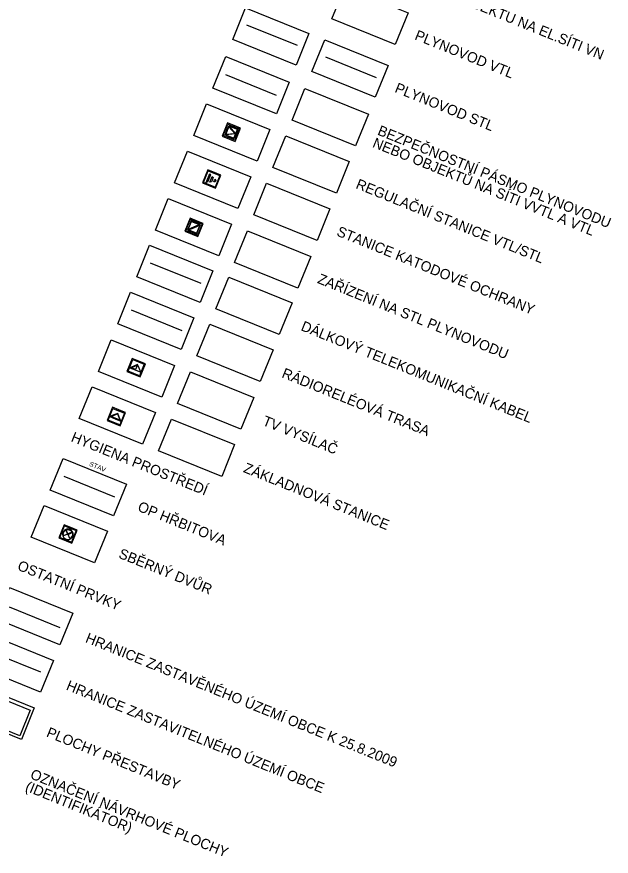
# Model space of a CAD drawing. Extents: x -522754 to -518969, y -1191121 to -1188171.
# Drawn here: x -520123 to -519254, y -1191121 to -1189893 of the extents above; entities that cross this region are included whole.
import ezdxf

# ---------------------------------------------------------------- set-up
doc = ezdxf.new("R2010")
doc.units = 0
for name, color, linetype in [('hr_zast_uz_P_n', 7, 'Continuous'), ('HZU_P_s', 7, 'Continuous'), ('Implicitní', 7, 'Continuous'), ('kabel_dal_s', 7, 'Continuous'), ('ložisk_nerost', 7, 'Continuous'), ('plyn_STL_n', 7, 'Continuous'), ('plyn_STL_s', 7, 'Continuous'), ('plyn_zar_STL_s', 7, 'Continuous'), ('RR_trasa_s', 7, 'Continuous'), ('sberny_dvur_s', 7, 'Continuous'), ('stan_KO_s', 7, 'Continuous'), ('TV_vysilac_s', 7, 'Continuous'), ('zakl_stan_s', 7, 'Continuous')]:
    doc.layers.add(name, color=color, linetype=linetype)

msp = doc.modelspace()

# ---------------------------------------------------------------- linework, layer by layer
at = {"layer": 'hr_zast_uz_P_n'}
msp.add_line((-520162.9, -1190821.2), (-520088.7, -1190851.2), dxfattribs=at)
at = {"layer": 'HZU_P_s'}
msp.add_line((-520134.5, -1190756.1), (-520060.4, -1190786.2), dxfattribs=at)
at = {"layer": 'Implicitní'}
for p, q in [((-519818.1, -1189977.4), (-519744, -1190007.5)), ((-520054.8, -1190564.9), (-519980.6, -1190594.9))]:
    msp.add_line(p, q, dxfattribs=at)
for points in [[(-519643.7, -1189849.5), (-519551, -1189887.1), (-519569.8, -1189933.4), (-519662.5, -1189895.8)], [(-519788.7, -1189879.6), (-519696, -1189917.2), (-519714.8, -1189963.5), (-519807.5, -1189925.9)], [(-519672.9, -1189926.6), (-519580.2, -1189964.1), (-519599, -1190010.5), (-519691.7, -1189972.9)], [(-519817.6, -1189950.9), (-519724.9, -1189988.4), (-519743.7, -1190034.8), (-519836.4, -1189997.2)], [(-519701.8, -1189997.8), (-519609.1, -1190035.4), (-519627.9, -1190081.7), (-519720.5, -1190044.2)], [(-519845.7, -1190020.2), (-519753, -1190057.8), (-519771.8, -1190104.1), (-519864.5, -1190066.5)], [(-519729.8, -1190067.1), (-519637.2, -1190104.7), (-519655.9, -1190151), (-519748.6, -1190113.5)], [(-519873.8, -1190089.5), (-519781.1, -1190127.1), (-519799.9, -1190173.4), (-519892.6, -1190135.8)], [(-519757.9, -1190136.4), (-519665.3, -1190174), (-519684, -1190220.3), (-519776.7, -1190182.8)], [(-519901.9, -1190158.8), (-519809.2, -1190196.4), (-519828, -1190242.7), (-519920.7, -1190205.1)], [(-519786, -1190205.8), (-519693.3, -1190243.3), (-519712.1, -1190289.7), (-519804.8, -1190252.1)], [(-519929.1, -1190226.8), (-519836.4, -1190264.3), (-519855.2, -1190310.7), (-519947.9, -1190273.1)], [(-519813.3, -1190273.7), (-519720.6, -1190311.3), (-519739.4, -1190357.6), (-519832, -1190320.1)], [(-519957, -1190295.6), (-519864.3, -1190333.2), (-519883.1, -1190379.5), (-519975.8, -1190342)], [(-519957, -1190295.6), (-519864.3, -1190333.2), (-519883.1, -1190379.5), (-519975.8, -1190342)], [(-519841.2, -1190342.6), (-519748.5, -1190380.1), (-519767.3, -1190426.5), (-519859.9, -1190388.9)], [(-519985.3, -1190365.4), (-519892.6, -1190402.9), (-519911.4, -1190449.3), (-520004.1, -1190411.7)], [(-519869.4, -1190412.3), (-519776.8, -1190449.9), (-519795.5, -1190496.2), (-519888.2, -1190458.7)], [(-520013.2, -1190434.2), (-519920.5, -1190471.8), (-519939.3, -1190518.1), (-520032, -1190480.6)], [(-520013.2, -1190434.2), (-519920.5, -1190471.8), (-519939.3, -1190518.1), (-520032, -1190480.6)], [(-519897.3, -1190481.2), (-519804.7, -1190518.7), (-519823.4, -1190565.1), (-519916.1, -1190527.5)], [(-520055.6, -1190539), (-519962.9, -1190576.5), (-519981.7, -1190622.9), (-520074.4, -1190585.3)], [(-520083.5, -1190607.8), (-519990.8, -1190645.4), (-520009.6, -1190691.7), (-520102.3, -1190654.2)], [(-520134.3, -1190727.5), (-520041.6, -1190765), (-520060.4, -1190811.4), (-520153, -1190773.8)], [(-520162.4, -1190797), (-520069.7, -1190834.5), (-520088.5, -1190880.9), (-520181.2, -1190843.3)], [(-520190.5, -1190866.2), (-520097.8, -1190903.8), (-520116.6, -1190950.1), (-520209.3, -1190912.6)], [(-520187.6, -1190872.9), (-520103.8, -1190907), (-520119.1, -1190944.5), (-520202.9, -1190910.4)]]:
    msp.add_lwpolyline(points, close=True, dxfattribs=at)
at = {"layer": 'kabel_dal_s'}
msp.add_line((-519928.3, -1190252.7), (-519854.1, -1190282.7), dxfattribs=at)
at = {"layer": 'ložisk_nerost'}
for points in [[(-519805.6, -1190052), (-519815.3, -1190048.1), (-519823, -1190067.4), (-519803.7, -1190075.2), (-519796, -1190055.9), (-519805.6, -1190052)], [(-519814.5, -1190049.8), (-519797.6, -1190056.6), (-519804.4, -1190073.5), (-519821.4, -1190066.7), (-519814.5, -1190049.8)], [(-519806.1, -1190053.2), (-519797.6, -1190056.6), (-519804.4, -1190073.5), (-519821.4, -1190066.7), (-519814.5, -1190049.8), (-519806.1, -1190053.2)], [(-519812, -1190068.4), (-519818.8, -1190065.7), (-519816.1, -1190059)], [(-519815.5, -1190059.2), (-519817.7, -1190064.6)], [(-519816.1, -1190058.9), (-519813.4, -1190052.2), (-519806.6, -1190054.9)], [(-519815.5, -1190059.2), (-519816.1, -1190058.9)], [(-519816.1, -1190059), (-519815.5, -1190059.2)], [(-519813.3, -1190053.7), (-519815.5, -1190059.2)], [(-519804.6, -1190063.6), (-519813.3, -1190053.7)], [(-519806.9, -1190055.5), (-519813, -1190053)], [(-519813, -1190053), (-519803.2, -1190064.1)], [(-519806.6, -1190054.9), (-519806.9, -1190055.5)], [(-519806.8, -1190055.5), (-519806.6, -1190054.9)], [(-519800.7, -1190058), (-519806.8, -1190055.5)], [(-519806.6, -1190054.9), (-519799.9, -1190057.6), (-519802.6, -1190064.4)], [(-519805.6, -1190052), (-519806.1, -1190053.2)], [(-519806.1, -1190053.2), (-519805.6, -1190052)], [(-519805.7, -1190070.3), (-519800.7, -1190058)], [(-519803.2, -1190064.1), (-519818, -1190065.4)], [(-519818, -1190065.4), (-519811.8, -1190067.9)], [(-519817.7, -1190064.6), (-519804.6, -1190063.6)], [(-519802.6, -1190064.4), (-519805.3, -1190071.2), (-519812, -1190068.4)], [(-519811.8, -1190067.9), (-519805.7, -1190070.3)]]:
    msp.add_lwpolyline(points, dxfattribs=at)
at = {"layer": 'plyn_STL_n'}
msp.add_line((-519671.7, -1189951.5), (-519597.5, -1189981.5), dxfattribs=at)
at = {"layer": 'plyn_STL_s'}
msp.add_line((-519787.5, -1189904.5), (-519713.4, -1189934.6), dxfattribs=at)
at = {"layer": 'plyn_zar_STL_s'}
for p, q in [((-519856.1, -1190196.9), (-519864.8, -1190200.6)), ((-519861.7, -1190194.7), (-519861.4, -1190194.1)), ((-519861.4, -1190194.1), (-519861.6, -1190194.7)), ((-519864.8, -1190200.6), (-519872.6, -1190203.9)), ((-519872.2, -1190204.7), (-519864.4, -1190201.4)), ((-519866.9, -1190207.6), (-519866.7, -1190207)), ((-519866.6, -1190207), (-519866.9, -1190207.6)), ((-519864.4, -1190201.4), (-519855.7, -1190197.8))]:
    msp.add_line(p, q, dxfattribs=at)
for points in [[(-519860.3, -1190191.2), (-519869.9, -1190187.3), (-519877.7, -1190206.6), (-519858.4, -1190214.4), (-519850.6, -1190195.1), (-519860.3, -1190191.2)], [(-519869.2, -1190189), (-519852.3, -1190195.8), (-519859.1, -1190212.7), (-519876, -1190205.9), (-519869.2, -1190189)], [(-519860.7, -1190192.4), (-519852.3, -1190195.8), (-519859.1, -1190212.7), (-519876, -1190205.9), (-519869.2, -1190189), (-519860.8, -1190192.4)], [(-519861.4, -1190194.1), (-519868.2, -1190191.3), (-519870.9, -1190198.1)], [(-519870.3, -1190198.3), (-519867.8, -1190192.2)], [(-519867.8, -1190192.2), (-519861.7, -1190194.7)], [(-519861.6, -1190194.7), (-519856.1, -1190196.9)], [(-519857.4, -1190203.6), (-519854.7, -1190196.8), (-519861.4, -1190194.1)], [(-519860.8, -1190192.4), (-519860.3, -1190191.2)], [(-519860.3, -1190191.2), (-519860.7, -1190192.4)], [(-519870.9, -1190198.1), (-519873.7, -1190204.9), (-519866.9, -1190207.6)], [(-519872.6, -1190203.9), (-519870.3, -1190198.3)], [(-519866.7, -1190207), (-519872.2, -1190204.7)], [(-519866.9, -1190207.6), (-519860.1, -1190210.3), (-519857.4, -1190203.6)], [(-519860.5, -1190209.5), (-519866.6, -1190207)], [(-519858, -1190203.3), (-519860.5, -1190209.5)], [(-519855.7, -1190197.8), (-519858, -1190203.3)]]:
    msp.add_lwpolyline(points, dxfattribs=at)
at = {"layer": 'RR_trasa_s'}
msp.add_line((-519956.2, -1190321.5), (-519882, -1190351.6), dxfattribs=at)
at = {"layer": 'sberny_dvur_s'}
for points in [[(-520044.5, -1190639.8), (-520054.1, -1190635.9), (-520062, -1190655.2), (-520042.7, -1190663), (-520034.9, -1190643.8), (-520044.5, -1190639.9)], [(-520053.4, -1190637.6), (-520036.5, -1190644.5), (-520043.4, -1190661.4), (-520060.3, -1190654.5), (-520053.4, -1190637.6)], [(-520045, -1190641), (-520036.5, -1190644.5), (-520043.4, -1190661.4), (-520060.3, -1190654.5), (-520053.4, -1190637.6), (-520045, -1190641)], [(-520056, -1190647.5), (-520056.2, -1190648.4), (-520056.3, -1190649.4), (-520056.3, -1190650.3), (-520056.2, -1190651.3), (-520055.9, -1190652.2), (-520055.5, -1190653.1), (-520055.1, -1190654), (-520054.5, -1190654.8), (-520053.8, -1190655.4), (-520053, -1190656), (-520052.2, -1190656.5), (-520051.6, -1190656.8)], [(-520055.8, -1190646.8), (-520056, -1190647.4), (-520056, -1190647.5)], [(-520054.9, -1190647.1), (-520055.8, -1190646.8)], [(-520045.8, -1190642.6), (-520046, -1190642.5), (-520046.9, -1190642.2), (-520047.9, -1190642.1), (-520048.9, -1190642), (-520049.8, -1190642.1), (-520050.8, -1190642.3), (-520051.7, -1190642.7), (-520052.6, -1190643.1), (-520053.4, -1190643.7), (-520054.1, -1190644.3), (-520054.7, -1190645), (-520055.3, -1190645.8), (-520055.7, -1190646.7), (-520055.7, -1190646.7)], [(-520055.7, -1190646.7), (-520054.9, -1190647.1)], [(-520055, -1190652.1), (-520055.2, -1190651.4), (-520055.3, -1190650.6), (-520055.4, -1190649.7), (-520055.4, -1190648.9), (-520055.2, -1190648.1), (-520055.1, -1190647.8)], [(-520055.1, -1190647.8), (-520054.9, -1190647.1)], [(-520049.1, -1190649.6), (-520055, -1190652.1)], [(-520054.9, -1190647.1), (-520054.6, -1190646.6)], [(-520054.6, -1190646.6), (-520054.2, -1190645.9), (-520053.7, -1190645.2), (-520053.1, -1190644.6), (-520052.4, -1190644.1), (-520051.6, -1190643.6)], [(-520051.6, -1190643.6), (-520049.1, -1190649.6)], [(-520051, -1190643.4), (-520050, -1190643.1), (-520049.2, -1190643), (-520048.3, -1190643), (-520047.5, -1190643.1), (-520046.7, -1190643.3), (-520046.1, -1190643.5)], [(-520048.5, -1190649.3), (-520051, -1190643.4)], [(-520042.5, -1190646.8), (-520048.5, -1190649.3)], [(-520048.3, -1190649.9), (-520042.3, -1190647.3)], [(-520045.8, -1190655.8), (-520048.3, -1190649.9)], [(-520045.7, -1190642.6), (-520046.1, -1190643.5)], [(-520046.1, -1190643.5), (-520045.8, -1190642.6)], [(-520046.1, -1190643.5), (-520045.9, -1190643.6), (-520045.1, -1190644), (-520044.4, -1190644.5), (-520043.8, -1190645.1), (-520043.2, -1190645.7), (-520042.5, -1190646.8)], [(-520042.2, -1190651.7), (-520042.4, -1190652.2), (-520042.7, -1190652.8), (-520043.1, -1190653.6), (-520043.7, -1190654.2), (-520044.3, -1190654.8), (-520044.9, -1190655.3), (-520045.8, -1190655.8)], [(-520041.3, -1190652), (-520041.1, -1190651), (-520041, -1190650.1), (-520041, -1190649.1), (-520041.1, -1190648.1), (-520041.4, -1190647.2), (-520041.8, -1190646.3), (-520042.3, -1190645.5), (-520042.8, -1190644.7), (-520043.5, -1190644), (-520044.3, -1190643.4), (-520045.1, -1190642.9), (-520045.7, -1190642.6)], [(-520045, -1190641), (-520044.5, -1190639.8)], [(-520044.5, -1190639.9), (-520045, -1190641)], [(-520042.3, -1190647.3), (-520042, -1190648.8), (-520041.9, -1190649.7), (-520042, -1190650.5), (-520042.1, -1190651.4), (-520042.2, -1190651.7)], [(-520041.3, -1190652.1), (-520042.2, -1190651.7)], [(-520042.2, -1190651.7), (-520041.3, -1190652)], [(-520051.6, -1190656.8), (-520051.5, -1190656.8)], [(-520051.5, -1190656.8), (-520051.3, -1190656.9), (-520050.4, -1190657.2), (-520049.4, -1190657.4), (-520048.4, -1190657.4), (-520047.5, -1190657.3), (-520046.5, -1190657.1), (-520045.6, -1190656.8), (-520044.7, -1190656.3), (-520043.9, -1190655.8), (-520043.2, -1190655.1), (-520042.6, -1190654.4), (-520042, -1190653.6), (-520041.6, -1190652.7), (-520041.3, -1190652.1)]]:
    msp.add_lwpolyline(points, dxfattribs=at)
at = {"layer": 'stan_KO_s'}
for points in [[(-519834.4, -1190120.5), (-519844.1, -1190116.6), (-519851.9, -1190135.8), (-519832.6, -1190143.7), (-519824.8, -1190124.4), (-519834.4, -1190120.5)], [(-519843.3, -1190118.2), (-519826.4, -1190125.1), (-519833.3, -1190142), (-519850.2, -1190135.1), (-519843.3, -1190118.2)], [(-519834.9, -1190121.7), (-519826.4, -1190125.1), (-519833.3, -1190142), (-519850.2, -1190135.1), (-519843.3, -1190118.2), (-519834.9, -1190121.7)], [(-519846.5, -1190135.2), (-519841.2, -1190122.2)], [(-519839.8, -1190123.9), (-519844.3, -1190135)], [(-519841.2, -1190122.2), (-519839.8, -1190123.9)], [(-519834.4, -1190120.5), (-519834.9, -1190121.7)], [(-519834.9, -1190121.7), (-519834.4, -1190120.5)], [(-519844.3, -1190135), (-519846.5, -1190135.2)], [(-519840.9, -1190134.7), (-519837.6, -1190126.4)], [(-519838.7, -1190134.5), (-519840.9, -1190134.7)], [(-519836.1, -1190128.1), (-519838.7, -1190134.5)], [(-519837.6, -1190126.4), (-519836.1, -1190128.1)], [(-519835.3, -1190134.3), (-519833.9, -1190130.6)], [(-519833.1, -1190134.1), (-519835.3, -1190134.3)], [(-519833.9, -1190130.6), (-519832.4, -1190132.3)], [(-519832.4, -1190132.3), (-519833.1, -1190134.1)]]:
    msp.add_lwpolyline(points, dxfattribs=at)
at = {"layer": 'TV_vysilac_s'}
for points in [[(-519944.9, -1190396.5), (-519954.5, -1190392.6), (-519962.3, -1190411.9), (-519943.1, -1190419.7), (-519935.3, -1190400.5), (-519944.9, -1190396.5)], [(-519953.8, -1190394.3), (-519936.9, -1190401.2), (-519943.8, -1190418.1), (-519960.7, -1190411.2), (-519953.8, -1190394.3)], [(-519945.4, -1190397.7), (-519936.9, -1190401.2), (-519943.8, -1190418.1), (-519960.7, -1190411.2), (-519953.8, -1190394.3), (-519945.4, -1190397.7)], [(-519952.1, -1190403.7), (-519958, -1190406.2)], [(-519958, -1190406.2), (-519950.2, -1190409.4)], [(-519956.4, -1190406.1), (-519951.9, -1190404.2)], [(-519949.6, -1190408.8), (-519956.4, -1190406.1)], [(-519944.3, -1190406.8), (-519946.6, -1190401.4), (-519952.1, -1190403.7)], [(-519952.1, -1190403.7), (-519951.9, -1190404.2)], [(-519951.9, -1190404.2), (-519952.1, -1190403.7)], [(-519951.9, -1190404.2), (-519946.9, -1190402.1)], [(-519946.9, -1190402.1), (-519949.6, -1190408.8)], [(-519944.9, -1190396.5), (-519945.4, -1190397.7)], [(-519945.4, -1190397.7), (-519944.9, -1190396.5)], [(-519950.2, -1190409.4), (-519941.8, -1190412.8)], [(-519941.8, -1190412.8), (-519944.3, -1190406.8)]]:
    msp.add_lwpolyline(points, dxfattribs=at)
at = {"layer": 'zakl_stan_s'}
for points in [[(-519973.9, -1190468), (-519983.5, -1190464.1), (-519991.3, -1190483.4), (-519972, -1190491.2), (-519964.2, -1190471.9), (-519973.9, -1190468)], [(-519982.8, -1190465.8), (-519965.9, -1190472.6), (-519972.7, -1190489.6), (-519989.7, -1190482.7), (-519982.8, -1190465.8)], [(-519974.3, -1190469.2), (-519965.9, -1190472.6), (-519972.7, -1190489.5), (-519989.7, -1190482.7), (-519982.8, -1190465.8), (-519974.4, -1190469.2)], [(-519981.2, -1190475.2), (-519987.2, -1190477.7)], [(-519987.2, -1190477.7), (-519979.4, -1190480.8)], [(-519985.5, -1190477.6), (-519981, -1190475.7)], [(-519978.5, -1190480.4), (-519985.5, -1190477.6)], [(-519973.5, -1190478.3), (-519975.8, -1190472.9), (-519981.2, -1190475.2)], [(-519981, -1190475.7), (-519976.1, -1190473.6)], [(-519976.1, -1190473.6), (-519974, -1190478.5)], [(-519974.4, -1190469.2), (-519973.9, -1190468)], [(-519973.9, -1190468), (-519974.3, -1190469.2)], [(-519974, -1190478.5), (-519973.5, -1190478.3)], [(-519973.5, -1190478.4), (-519974, -1190478.6)], [(-519974, -1190478.6), (-519972.1, -1190483)], [(-519971, -1190484.3), (-519973.5, -1190478.4)], [(-519979.4, -1190480.8), (-519971, -1190484.3)], [(-519972.1, -1190483), (-519978.5, -1190480.4)]]:
    msp.add_lwpolyline(points, dxfattribs=at)

# ---------------------------------------------------------------- texts
at = {"layer": 'Implicitní'}
for s, height, rotation, p in [('OP OBJEKTU NA EL.SÍTI VN', 15, 337.9379, (-519515.1, -1189856.1)), ('PLYNOVOD VTL', 15, 337.9379, (-519542.4, -1189925.6)), ('PLYNOVOD STL', 15, 337.9379, (-519571.6, -1190002.7)), ('BEZPEČNOSTNÍ PÁSMO PLYNOVODU ', 15, 337.9379, (-519596.8, -1190065)), ('NEBO OBJEKTŮ NA SÍTI VVTL A VTL', 15, 337.9379, (-519604.1, -1190083)), ('REGULAČNÍ STANICE VTL/STL', 15, 337.9379, (-519628.6, -1190143.3)), ('STANICE KATODOVÉ OCHRANY', 15, 337.9379, (-519656.6, -1190212.6)), ('ZAŘÍZENÍ NA STL PLYNOVODU', 15, 337.9379, (-519684.7, -1190281.9)), ('DÁLKOVÝ TELEKOMUNIKAČNÍ KABEL', 15, 337.9379, (-519708.9, -1190351.1)), ('RÁDIORELÉOVÁ TRASA', 15, 337.9379, (-519736.9, -1190419.9)), ('TV VYSÍLAČ', 15, 337.9379, (-519765.1, -1190489.7)), ('HYGIENA PROSTŘEDÍ', 15, 337.9381, (-520045.2, -1190513.4)), ('STAV', 7, 337.9379, (-520018.1, -1190549.5)), ('ZÁKLADNOVÁ STANICE', 15, 337.9379, (-519793, -1190558.5)), ('OP HŘBITOVA', 15, 337.9381, (-519947.8, -1190615)), ('SBĚRNÝ DVŮR', 15, 337.9381, (-519975.7, -1190683.8)), ('OSTATNÍ PRVKY', 15, 337.9381, (-520123.7, -1190701.3)), ('HRANICE ZASTAVĚNÉHO ÚZEMÍ OBCE K 25.8.2009', 15, 337.9381, (-520024.2, -1190807.2)), ('HRANICE ZASTAVITELNÉHO ÚZEMÍ OBCE', 15, 337.9381, (-520052.3, -1190876.7)), ('PLOCHY PŘESTAVBY', 15, 337.8143, (-520081.2, -1190945.2)), ('OZNAČENÍ NÁVRHOVÉ PLOCHY ', 15, 337.9381, (-520104.9, -1191006.4)), ('(IDENTIFIKÁTOR)', 15, 337.9381, (-520112.2, -1191024.4))]:
    msp.add_text(s, height=height, rotation=rotation, dxfattribs=at).set_placement(p)

doc.saveas('drawing.dxf')
